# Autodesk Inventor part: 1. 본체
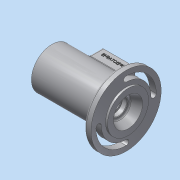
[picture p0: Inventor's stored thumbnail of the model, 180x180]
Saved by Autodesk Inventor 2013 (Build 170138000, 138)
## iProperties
Created: 2017-05
Part Number: 1. 본체
Material: 알루미늄 6061
Document SubType Name: Modeling
Designer: dgall
Density: 2.71 g/cm^3
Mass: 678.685 g
Surface Area: 618.179 cm^2
Volume: 250.437 cm^3
Author: dgall
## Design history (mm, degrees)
sketch "스케치1"
  geometry: L1 (-57.5, 0)-(57.5, 0); L2 (-57.5, 31)-(44.5, 31); L3 (44.5, 31)-(44.5, 53); L4 (44.5, 53)-(54.5, 53); L5 (54.5, 53)-(54.5, 31); L6 (54.5, 31)-(57.5, 31); L7 (57.5, 31)-(57.5, 22); L8 (57.5, 22)-(43.5, 16); L9 (43.5, 16)-(43.5, 12.5); L10 (43.5, 12.5)-(36.2, 12.5); L11 (36.2, 12.5)-(36.2, 10); L12 (36.2, 10)-(33.5, 10); L13 (33.5, 10)-(33.5, 16.5); L14 (33.5, 16.5)-(28.5, 16.5); L15 (28.5, 16.5)-(28.5, 17.5); L16 (28.5, 17.5)-(17.5, 17.5); L17 (17.5, 17.5)-(17.5, 26); L18 (17.5, 26)-(-20.5, 26); L19 (-20.5, 26)-(-20.5, 17.5); L20 (-20.5, 17.5)-(-31.5, 17.5); L21 (-31.5, 17.5)-(-31.5, 18.5); L22 (-31.5, 18.5)-(-33.25, 18.5); L23 (-33.25, 18.5)-(-33.25, 17.5); L24 (-33.25, 17.5)-(-36.5, 17.5); L25 (-36.5, 17.5)-(-36.5, 20); L26 (-36.5, 20)-(-45.5, 20); L27 (-45.5, 20)-(-45.5, 24); L28 (-45.5, 24)-(-48.5, 24); L29 (-48.5, 24)-(-48.5, 21); L30 (-48.5, 21)-(-57.5, 21); L31 (-57.5, 31)-(-57.5, 21); 2 further points
  constraints: 62 end point, 12 parallel, 9 vertical alignment, 1 coincident, 1 collinear, 1 horizontal, 1 horizontal alignment, 1 midpoint, 1 perpendicular, 1 vertical
  dimensions: "d0" = 115 distance of L1.start L1.end; "d2" = 106 diameter of L4 L1; "d3" = 62 diameter of L6 L1; "d4" = 3 distance of L5.end L6.end; "d5" = 13 distance between parallel lines of L3 L7; "d6" = 44 diameter of L7.end L1; "d8" = 14 horizontal distance of L7.end L8.end; "d9" = 32 diameter of L8.end L1; "d10" = 25 diameter of L10 L1; "d11" = 20 diameter of L12 L1; "d12" = 7.3 distance of L9.end L10.end; "d13" = 2.7 distance of L11.end L12.end; "d14" = 33 diameter of L14 L1; "d15" = 35 diameter of L16 L1; "d16" = 42 diameter of L30 L1; "d17" = 48 diameter of L28 L1; "d18" = 40 diameter of L26 L1; "d19" = 35 diameter of L24 L1; "d20" = 37 diameter of L22 L1; "d21" = 35 diameter of L20 L1; "d22" = 52 diameter of L18 L1; "d23" = 3 distance of L27.end L28.end; "d24" = 12 distance between parallel lines of L27 L31; "d25" = 21 distance between parallel lines of L25 L31; "d27" = 38 distance of L17.end L18.end; "d29" = 10 distance between parallel lines of L9 L13; "d30" = 11 distance of L19.end L20.end; "d31" = 1.75 distance of L21.end L22.end; "d34" = 26 distance between parallel lines of L21 L31; "d35" = 60 distance between parallel lines of L21 L15
revolve "회전1" sketch "스케치1" stored, may be unused: angle "d36" = 90 deg
feature "스레드1" dims "d37" = 10, "d38" = 0
chamfer "모따기1" distance "d39" = 1; stored, may be unused: second distance "d40" = 2, angle "d41" = 45 deg
chamfer "모따기2" distance "d42" = 0.7; stored, may be unused: second distance "d43" = 2, angle "d44" = 30 deg
fillet "모깎기1" dims "d45" = 3
fillet "모깎기2" dims "d46" = 3
chamfer "모따기3" distance "d47" = 1; stored, may be unused: second distance "d48" = 2, angle "d49" = 30 deg
node "작업 평면1"
sketch "스케치2"
  geometry: L1 (26.5, -20)-(-23.5, -20); L2 (-23.5, -20)-(-23.5, 20); L3 (-23.5, 20)-(26.5, 20); L4 (26.5, 20)-(26.5, -20); L5 (56.5, 21)-(56.5, -21) reference; L6 (-14.5, -11)-(17.5, -11); L7 (17.5, -11)-(17.5, 11); L8 (17.5, 11)-(-14.5, 11); L9 (-14.5, 11)-(-14.5, -11); L10 (57.5, 31)-(57.5, -31) reference; 3 further points
  constraints: 16 end point, 4 parallel, 2 midpoint, 2 perpendicular, 1 horizontal, 1 horizontal alignment, 3 other
  dimensions: "d51" = 40 distance of L3.end L1.start; "d53" = 50 distance of L1.start L1.end; "d55" = 32 distance of L6.start L6.end; "d103" = 56 distance from line of L10 point (1.5, -20)
extrude "돌출1" join sketch "스케치2" stored distance "d56" = 10; taper "d57" = 0 deg
fillet "모깎기3" dims "d58" = 3
fillet "모깎기4" dims "d59" = 3
fillet "모깎기5" dims "d60" = 3
sketch "스케치3"
  geometry: L1 (-17.5, -8)-(-17.5, 8) reference; L2 (-14.5, 11)-(11.5, 11) reference; L3 (14.5, 8)-(14.5, -8) reference; L4 (11.5, -11)-(-14.5, -11) reference; A1 r 3 centre (-14.5, 8) between (-14.5, 11) and (-17.5, 8) reference; A2 r 3 centre (11.5, 8) between (14.5, 8) and (11.5, 11) reference; A3 r 3 centre (11.5, -8) between (11.5, -11) and (14.5, -8) reference; A4 r 3 centre (-14.5, -8) between (-17.5, -8) and (-14.5, -11) reference; 1 further point
extrude "돌출2" cut sketch "스케치3" stored distance "d61" = 10; taper "d62" = 0 deg
chamfer "모따기4" distance "d63" = 1; stored, may be unused: second distance "d64" = 2, angle "d65" = 30 deg
fillet "모깎기6" dims "d66" = 0.3
fillet "모깎기7" dims "d67" = 0.3
fillet "모깎기8" dims "d68" = 3
chamfer "모따기5" distance "d69" = 1; stored, may be unused: second distance "d70" = 2, angle "d71" = 30 deg
sketch "스케치4"
  geometry: L1 (11.5, 12)-(-14.5, 12) reference; 7 further points
  constraints: 2 horizontal alignment, 2 midpoint, 1 coincident, 1 vertical alignment
  dimensions: "d72" = 31 distance of point (-22, -15.5) point (-22, 15.5); "d74" = 41 distance of point (19, 15.5) point (-22, 15.5); "d76" = 15.5 vertical distance of point (0, 0) point (-22, 15.5); "d77" = 15.5 vertical distance of point (0, 0) point (-22, -15.5); "d102" = 20.5 horizontal distance of point (-1.5, 12) point (-22, 15.5)
hole "구멍1" sketch "스케치4" at (-22, 15.5), (-22, -15.5), (19, -15.5), (19, 15.5) diameter "d78" = 2.459; stored, may be unused: countersink angle "d82" = 90 deg, drill point angle "d84" = 118 deg; dims "d79" = 6, "d80" = 4, "d81" = 2, "d83" = 8
sketch "스케치5"
  geometry: C1 r 31 at (0, 0) reference; C2 r 53 at (0, 0) reference; A1 r 41.5 centre (0, 0) between (-41.5, 0) and (0, 41.5); A2 r 4 centre (-41.5, 0) between (-45.5, 0) and (-37.5, 0); A3 r 4 centre (0, 41.5) between (0, 37.5) and (0, 45.5); A4 r 4 centre (41.5, 0) between (45.5, 0) and (37.5, 0); A5 r 4 centre (0, -41.5) between (0, -37.5) and (0, -45.5); A6 r 45.5 centre (0, 0) between (0, 45.5) and (-45.5, 0); A7 r 45.5 centre (0, 0) between (0, -45.5) and (45.5, 0); A8 r 37.5 centre (0, 0) between (0, 37.5) and (-37.5, 0); A9 r 37.5 centre (0, 0) between (0, -37.5) and (37.5, 0); 1 further point
  constraints: 20 point on circle, 9 centre point, 3 coincident, 2 horizontal alignment, 2 vertical alignment
  dimensions: "d85" = 83 diameter of A1; "d88" = 45.5 radius of A6; "d89" = 37.5 radius of A8; "d90" = 4 radius of A3; "d91" = 4 radius of A2; "d92" = 45.5 radius of A7; "d93" = 37.5 radius of A9; "d94" = 4 radius of A5; "d95" = 4 radius of A4
extrude "돌출3" cut sketch "스케치5" stored distance "d96" = 10; taper "d97" = 0 deg
sketch "스케치6"
  geometry: L1 (44, 0)-(0, 0) reference; L2 (-34, -75)-(-34, -13) reference; 2 further points
  constraints: 1 other
  dimensions: "d98" = 56 distance from line of point (22, -8) L2; "d99" = 8 distance from line of point (22, -8) L1
feature "엠보싱1" sketch "스케치6" dims "d0" = 115, "d2" = 106, "d3" = 62, "d4" = 3, "d5" = 13, "d6" = 44, "d8" = 14, "d9" = 32, "d10" = 25, "d11" = 20, "d12" = 7.3, "d13" = 2.7, "d14" = 33, "d15" = 35, "d16" = 42, "d17" = 48, "d18" = 40, "d19" = 35, "d20" = 37, "d21" = 35, "d22" = 52, "d23" = 3, "d24" = 12, "d25" = 21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
fillet "모깎기9" dims "d104" = 3
node "솔리드1"
other parameters: "d50" = 44, "d86" = 91, "d87" = 75
